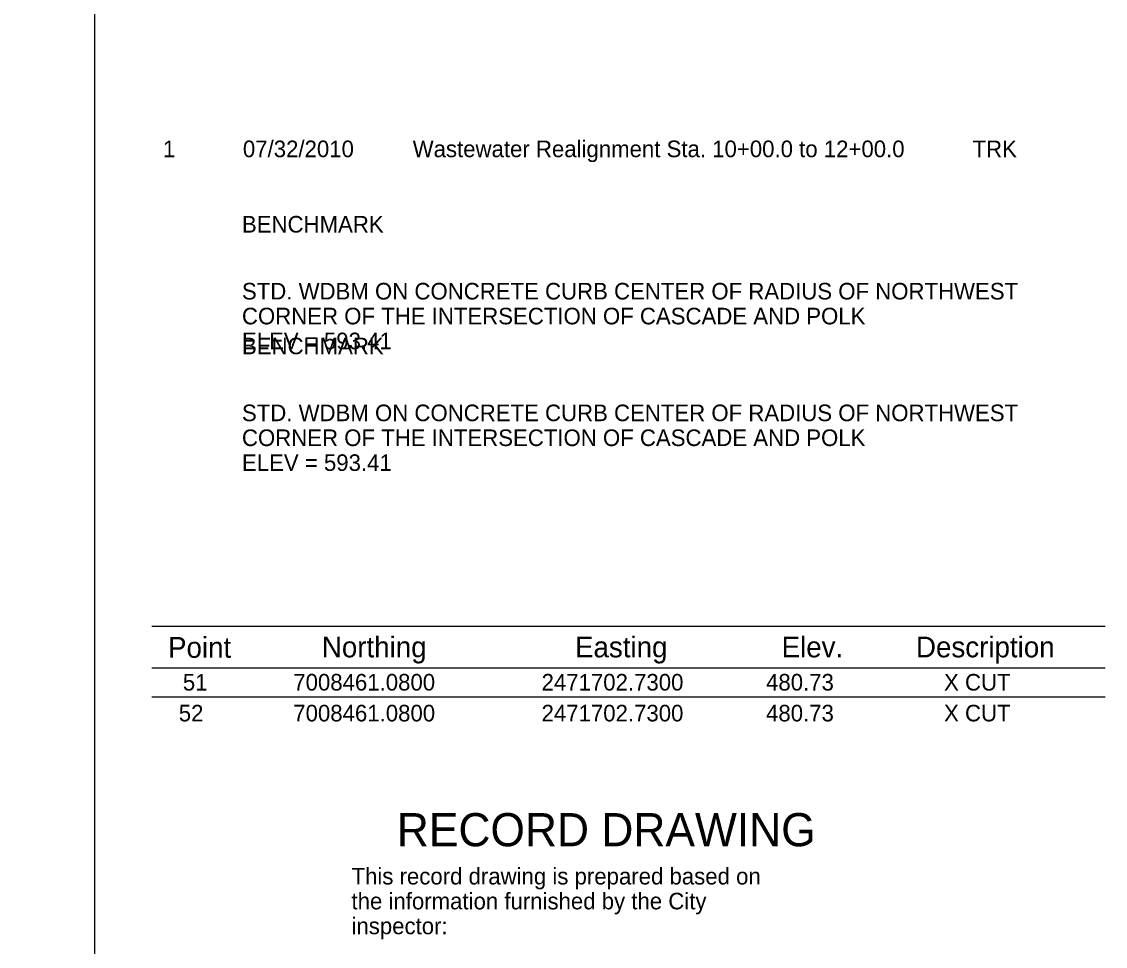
# Model space of a CAD drawing. Extents: x -3581 to -1895, y -2553 to -1611.
# Drawn here: x -2178.4 to -1917, y -2312.8 to -2089.8 of the extents above; entities that cross this region are included whole.
import ezdxf

# ---------------------------------------------------------------- set-up
doc = ezdxf.new("R2010")
doc.units = 0
for name, color, linetype in [('G_BORDER', 7, 'Continuous'), ('G_SHEET_EDGE', 7, 'Continuous'), ('G_SIGNATURE BLOCK', 7, 'Continuous')]:
    doc.layers.add(name, color=color, linetype=linetype)

msp = doc.modelspace()

# ---------------------------------------------------------------- linework, layer by layer
at = {"layer": 'G_BORDER'}
for p, q in [((-2147.05, -2235.59), (-1917.05, -2235.59)), ((-2147.05, -2245.59), (-1917.05, -2245.59)), ((-2147.05, -2252.59), (-1917.05, -2252.59))]:
    msp.add_line(p, q, dxfattribs=at)
at = {"layer": 'G_SHEET_EDGE'}
msp.add_lwpolyline([(-2160.75, -1621.96), (-3580.75, -1621.96), (-3580.75, -2541.96), (-2160.75, -2541.96)], close=True, dxfattribs=at)

# ---------------------------------------------------------------- texts
at = {"layer": 'G_BORDER'}
for s, height, p in [('1', 4, (-2144.35, -2122.46)), ('07/32/2010', 4, (-2125.06, -2122.46)), ('Wastewater Realignment Sta. 10+00.0 to 12+00.0', 4, (-2084.11, -2122.46)), ('TRK', 4, (-1949.09, -2122.46)), ('BENCHMARK', 4, (-2125.29, -2140.64)), ('STD. WDBM ON CONCRETE CURB CENTER OF RADIUS OF NORTHWEST', 4, (-2125.29, -2156.78)), ('CORNER OF THE INTERSECTION OF CASCADE AND POLK', 4, (-2125.29, -2162.78)), ('ELEV = 593.41', 4, (-2125.29, -2168.78)), ('BENCHMARK', 4, (-2125.29, -2169.99)), ('STD. WDBM ON CONCRETE CURB CENTER OF RADIUS OF NORTHWEST', 4, (-2125.29, -2186.13)), ('CORNER OF THE INTERSECTION OF CASCADE AND POLK', 4, (-2125.29, -2192.13)), ('ELEV = 593.41', 4, (-2125.29, -2198.13)), ('Point', 5, (-2143.12, -2243.19)), ('Northing', 5, (-2106.02, -2243.09)), ('Easting', 5, (-2044.96, -2243.09)), ('Elev.', 5, (-1995.13, -2243.09)), ('Description', 5, (-1962.72, -2243.09)), ('51', 4, (-2139.54, -2251.09)), ('7008461.0800', 4, (-2112.91, -2251.09)), ('2471702.7300', 4, (-2053.02, -2251.09)), ('480.73', 4, (-1998.88, -2251.09)), ('X CUT', 4, (-1955.95, -2251.09)), ('52', 4, (-2140.53, -2258.54)), ('7008461.0800', 4, (-2112.91, -2258.54)), ('2471702.7300', 4, (-2053.02, -2258.54)), ('480.73', 4, (-1998.88, -2258.54)), ('X CUT', 4, (-1955.95, -2258.54))]:
    msp.add_text(s, height=height, dxfattribs=at).set_placement(p)
at = {"layer": 'G_SIGNATURE BLOCK'}
msp.add_text('RECORD DRAWING', height=8, rotation=360, dxfattribs=at).set_placement((-2087.94, -2288.65))
for s, p in [('This record drawing is prepared based on', (-2098.87, -2297.87)), ('the information furnished by the City', (-2098.87, -2303.87)), ('inspector:', (-2098.87, -2309.87))]:
    msp.add_text(s, height=4, dxfattribs=at).set_placement(p)

doc.saveas('drawing.dxf')
